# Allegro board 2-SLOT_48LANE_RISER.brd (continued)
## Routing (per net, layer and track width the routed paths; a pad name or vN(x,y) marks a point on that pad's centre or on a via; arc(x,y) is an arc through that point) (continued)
PE_SLOT1_RX_DN<13>: length 121.3
  IN2 w0.089: v5(128.89,79.56) 129.07,79.38 129.07,77.6 129.03,77.55 129.03,77.53
  IN2 w0.145: J1.A73 222.2,34.51 222.4,34.44 222.54,34.52 222.68,34.66 222.68,38.06 222.53,38.35 222.08,38.73 221.76,39.04 221.69,39.45 221.69,40.24 221.59,40.77 220.94,41.7 220.29,42.63 220.12,43.61 220.12,43.61 219.96,44.54 219.84,44.62 219.72,45.33 219.8,45.45 219.7,46.02 219.62,46.07 219.48,46.84 219.54,46.92 219.19,48.86 218.18,50.31 216.27,51.64 215.22,51.83 215.09,51.74 214.6,51.82 214.51,51.95 214.11,52.02 213.98,51.93 213.49,52.02 213.4,52.15 211.82,52.43 205.03,53.62 204.21,53.77 204.08,53.68 203.59,53.76 203.5,53.9 203.1,53.96 202.97,53.87 202.48,53.96 202.39,54.09 201.56,54.24 200.16,54.48 191.93,53.03 143.93,61.5 139.47,64.62 139.33,64.59 138.73,65.01 138.7,65.15 138.23,65.49 138.05,65.45 137.49,65.85 137.46,66.02 136.99,66.36 136.82,66.33 136.25,66.73 136.22,66.89 135.74,67.23 135.56,67.19 135.01,67.58 134.98,67.76 133.76,68.62 131.5,70.88 131.32,70.88 130.94,71.26 130.94,71.43 129.03,73.35 129.03,74.31 128.87,74.47 128.87,75 129.03,75.15 129.03,75.59 128.89,75.72 128.89,76.25 129.03,76.39 129.03,77.53
  BOTTOM w0.135: U1.R4 v5(128.89,79.56)
PE_SLOT1_RX_DN<14>: length 118.6
  IN2 w0.089: 127.35,77.36 127.35,77.38 127.39,77.42 127.39,77.63 126.69,78.32 126.69,79 126.91,79.22 126.91,79.78 v5(127.29,80.36)
  IN2 w0.145: J1.A77 218.2,34.51 218.4,34.44 218.54,34.52 218.68,34.66 218.68,37.73 218.61,38.12 218.4,38.53 218.09,38.85 217.71,39.39 217.71,40.13 217.55,41 216.23,42.88 215.99,44.29 216.24,45.72 216.09,46.56 215.87,46.88 215.64,47.19 215.51,47.22 215.12,47.78 215.14,47.91 215.14,47.92 214.79,48.42 210.68,51.29 200.06,53.19 192.77,51.9 142.55,60.76 133.16,67.33 127.35,73.14 127.35,77.36
  BOTTOM w0.135: U1.U5 v5(127.29,80.36)
PE_SLOT1_RX_DN<15>: length 116.2
  IN2 w0.089: v5(126.49,80.36) 126.11,79.78 126.11,77.84 126.25,77.7 126.25,77.01 126.21,76.96 126.21,76.94
  IN2 w0.145: 126.21,76.94 126.21,72.58 133.99,64.8 140.65,60.13 192.88,50.92 199.74,52.13 208.15,50.65 208.35,50.51 208.35,50.51 208.37,50.35 208.76,50.08 208.92,50.11 210.07,49.3 210.08,49.3 211.61,48.22 212.59,46.83 213.67,40.72 213.67,40.03 213.8,39.25 214.68,38 214.68,34.66 214.54,34.52 214.4,34.44 214.2,34.51 J1.A81
  BOTTOM w0.135: U1.V5 v5(126.49,80.36)
PE_SLOT1_RX_DP<0>: length 162
  IN2 w0.089: v5(137.69,85.16) 138.22,85.53 141.16,85.53 142.29,86.67 143.16,86.67 143.21,86.71 143.23,86.71
  IN2 w0.145: J1.A16 278.46,34 278.52,34.2 278.7,34.29 278.97,34.55 278.97,38.23 277.93,39.27 277.93,40.74 277.57,41.25 276.31,43.04 276.01,44.74 274.93,46.29 255.86,59.64 196.49,70.11 188.2,75.92 161.63,80.6 155.06,85.2 152.33,85.68 152.33,85.68 146.48,86.71 143.23,86.71
  BOTTOM w0.135: U1.E11 v5(137.69,85.16)
PE_SLOT1_RX_DP<1>: length 159.6
  IN2 w0.089: v5(137.69,84.36) 138.22,84.73 138.74,84.73 138.94,84.94 139.8,84.94 140.08,84.66 143.22,84.66 143.26,84.7 143.28,84.7
  IN2 w0.145: 143.28,84.7 144.63,84.7 155.99,82.7 160.11,79.82 186.96,75.08 195.61,69.03 198.26,68.56 254.13,58.71 268.04,48.97 268.13,48.48 267.51,47.6 267.56,47.33 267.78,47.17 268.05,47.22 268.67,48.1 269.16,48.19 270.58,47.2 272.09,45.03 272.59,42.19 273.97,40.23 273.97,39.22 272.97,38.22 272.97,34.67 273.12,34.52 273.26,34.44 273.46,34.51 J1.A21
  BOTTOM w0.135: U1.E10 v5(137.69,84.36)
PE_SLOT1_RX_DP<2>: length 152.9
  IN2 w0.089: 143.28,83.18 143.26,83.18 143.22,83.13 142.71,83.13 142.47,83.38 139.88,83.38 139.64,83.13 138.22,83.13 v5(137.69,82.76)
  IN2 w0.145: J1.A25 269.46,34.51 269.26,34.44 269.26,34.45 269.12,34.52 268.97,34.67 268.97,38.15 269.95,39.14 269.95,40.76 267.97,43.58 267.7,45.11 265.13,48.78 252.1,57.9 198.26,67.4 194.17,68.12 185.73,74.03 159.49,78.65 155.02,81.78 145.95,83.38 143.76,83.18 143.28,83.18
  BOTTOM w0.135: U1.E8 v5(137.69,82.76)
PE_SLOT1_RX_DP<3>: length 152.2
  IN2 w0.089: v5(137.69,81.96) 138.22,82.33 138.74,82.33 138.94,82.54 140.82,82.54 140.83,82.53 142.73,82.2 143.22,82.2 143.26,82.24 143.28,82.24
  IN2 w0.145: J1.A29 265.46,34.51 265.26,34.44 265.12,34.52 264.97,34.67 264.97,38.26 263.97,39.26 263.97,40.37 263.7,41.89 263.52,42.15 263.41,42.31 262.84,45.57 262.82,45.63 262.1,46.65 261.35,47.73 260.85,47.82 260.32,47.45 260.12,47.48 259.91,47.78 259.95,47.98 260.48,48.35 260.56,48.85 260.28,49.26 259.78,49.35 258.89,48.72 258.62,48.77 258.47,48.99 258.52,49.26 259.41,49.88 259.49,50.38 258.85,51.29 250.77,56.95 240.97,58.68 198.31,66.2 198.26,66.21 193.61,67.19 185.38,72.96 159.25,77.56 154.74,80.72 146.12,82.24 143.28,82.24
  BOTTOM w0.135: U1.E7 v5(137.69,81.96)
PE_SLOT1_RX_DP<4>: length 143.2
  IN2 w0.089: v5(137.69,80.36) 138.22,80.73 139.34,80.73 140.16,80.88 142.87,80.88 142.91,80.92 142.94,80.92
  IN2 w0.145: J1.A35 259.46,34.51 259.26,34.44 259.12,34.52 258.97,34.67 258.97,38.24 259.97,39.24 259.97,40.33 259.88,40.88 259.88,40.88 258.64,42.64 258.4,42.88 257.87,43.63 257.49,45.81 252.28,53.24 248.01,56.23 236.29,58.3 236.23,58.31 198.26,65.01 193.48,65.85 184.99,71.8 158.51,76.46 154.41,79.33 145.37,80.92 142.94,80.92
  BOTTOM w0.135: U1.E5 v5(137.69,80.36)
PE_SLOT1_RX_DP<5>: length 141.8
  IN2 w0.089: v5(137.69,79.56) 138.22,79.93 138.74,79.93 138.94,80.14 141.94,80.14 142.22,79.86 142.61,79.86 142.65,79.9 142.68,79.9
  IN2 w0.145: 142.68,79.9 145.23,79.9 153.43,78.46 155.01,77.35 155.1,76.86 154.58,76.11 154.63,75.85 154.85,75.69 155.11,75.74 155.63,76.48 156.13,76.57 158.1,75.19 184.3,70.57 192.36,64.92 245.15,55.62 249.74,52.4 253.27,47.37 254.03,43.05 255.05,41.59 255.85,40.76 255.96,40.15 255.96,39.24 254.97,38.25 254.97,34.67 255.12,34.52 255.26,34.44 255.46,34.51 J1.A39
  BOTTOM w0.135: U1.E4 v5(137.69,79.56)
PE_SLOT1_RX_DP<6>: length 134.8
  IN2 w0.089: 141.12,78.3 141.1,78.3 141.05,78.26 140.08,78.26 139.8,78.54 138.94,78.54 138.74,78.33 138.22,78.33 v5(137.69,77.96)
  IN2 w0.145: J1.A43 251.46,34.51 251.26,34.44 251.12,34.52 250.97,34.67 250.97,38.21 251.94,39.19 251.94,39.97 251.82,40.69 250.32,42.84 249.86,45.42 245.15,52.15 240.8,55.2 190.59,64.05 183.2,69.22 155.13,74.18 149.82,77.89 144.86,78.77 143.84,78.77 143.28,78.66 141.4,78.3 141.12,78.3
  BOTTOM w0.135: U1.E2 v5(137.69,77.96)
PE_SLOT1_RX_DP<7>: length 132.4
  IN2 w0.089: v5(137.69,77.16) 138.22,77.53 140.7,77.53 140.74,77.58 140.77,77.58
  IN2 w0.145: J1.A47 247.46,34.51 247.26,34.44 247.12,34.52 246.97,34.67 246.97,38.23 246.02,39.17 246.02,40.7 245.89,41.45 243.51,44.84 242.42,51.05 241.73,52.03 238.11,54.56 189.65,63.11 182.8,67.9 154.81,72.84 152.51,74.45 152.01,74.36 151.4,73.48 151.13,73.43 150.91,73.59 150.86,73.85 151.48,74.74 151.39,75.23 149.05,76.87 145.03,77.58 140.77,77.58
  BOTTOM w0.135: U1.E1 v5(137.69,77.16)
PE_SLOT1_RX_DP<8>: length 129.3
  IN2 w0.089: 135.71,76.68 135.71,76.7 135.66,76.75 135.66,79.78 v5(135.29,80.36)
  IN2 w0.145: 135.71,76.68 135.71,76.33 135.94,76.1 139.52,76.1 140.06,76.63 140.55,76.63 143.28,76.15 146.41,75.6 150.92,72.44 155.28,71.67 155.28,71.67 182.23,66.92 189.21,62.04 225.33,55.67 237.76,46.96 238.59,45.78 241.97,40.95 241.97,39.36 242.95,38.38 242.95,34.54 242.7,34.29 242.52,34.2 242.46,34 J1.A52
  BOTTOM w0.135: U1.H5 v5(135.29,80.36)
PE_SLOT1_RX_DP<9>: length 126.9
  IN2 w0.089: v5(134.49,80.36) 134.86,79.78 134.86,79.25 135.1,79.01 135.1,78.18 134.69,77.76 134.69,77.7 134.67,77.68
  IN2 w0.145: 134.67,77.68 134.43,77.44 134.43,76.34 136.04,74.73 141.06,74.73 146.41,73.78 150.11,71.19 181.82,65.6 188.23,61.11 223.46,54.89 231.22,49.46 233.68,47 235.41,44.53 237.97,40.58 237.97,39.34 238.96,38.34 238.96,34.55 238.7,34.29 238.52,34.2 238.51,34.19 238.45,34.01 J1.A56
  BOTTOM w0.135: U1.J5 v5(134.49,80.36)
PE_SLOT1_RX_DP<10>: length 125.6
  IN2 w0.089: v5(132.89,80.36) 133.26,79.78 133.26,77.95 132.69,77.37 132.69,76.7 132.73,76.66 132.73,76.64
  IN2 w0.145: J1.A60 234.49,33.94 234.58,34.23 234.7,34.29 234.97,34.55 234.97,38.34 233.99,39.31 233.99,40.41 233.88,41.08 231.82,44.02 227.8,49.76 221.24,54.36 186.22,60.53 186.22,60.53 181.02,64.17 135.37,72.22 134.32,72.95 134.06,73.33 133.82,74.71 132.73,75.79 132.73,76.64
  BOTTOM w0.135: U1.L5 v5(132.89,80.36)
PE_SLOT1_RX_DP<11>: length 123.7
  IN2 w0.089: v5(132.09,80.36) 132.46,79.78 132.46,79.25 132.74,78.97 132.74,78.51 131.86,77.63 131.86,76.8 131.91,76.76 131.91,76.74
  IN2 w0.145: 131.91,76.74 131.91,74.93 132.43,74.41 132.66,73.08 133.02,72.56 135.03,71.16 179.76,63.27 184.63,59.86 219.53,53.71 222.39,51.89 229.71,41.43 229.97,40 229.97,39.35 230.96,38.35 230.96,34.55 230.7,34.29 230.51,34.19 230.45,34.01 J1.A64
  BOTTOM w0.135: U1.M5 v5(132.09,80.36)
PE_SLOT1_RX_DP<12>: length 123.2
  IN2 w0.089: v5(129.69,80.36) 130.06,79.78 130.06,78.12 130.3,77.88 130.3,77.29 130.35,77.25 130.35,77.23
  IN2 w0.145: J1.A68 226.46,34 226.52,34.2 226.7,34.29 226.96,34.55 226.96,38.35 225.98,39.34 225.98,40.37 225.8,41.38 224.56,43.15 224.07,45.95 223.68,46.5 223.68,46.51 222.65,47.99 220.7,50.77 217.59,52.94 215.39,53.33 200.72,55.92 191.62,54.31 144.62,62.6 134.44,69.72 130.95,73.22 130.95,74.87 130.35,75.47 130.35,77.23
  BOTTOM w0.135: U1.P5 v5(129.69,80.36)
PE_SLOT1_RX_DP<13>: length 121.2
  IN2 w0.089: 129.31,77.53 129.31,77.55 129.26,77.6 129.26,79.78 v5(128.89,80.36)
  IN2 w0.145: 129.31,77.53 129.31,73.46 133.94,68.83 144.04,61.76 191.93,53.32 200.16,54.77 201.6,54.51 201.67,54.5 201.68,54.5 202.02,54.44 216.38,51.91 218.38,50.51 219.46,48.97 220.56,42.74 221.17,41.86 221.86,40.88 221.97,40.26 221.97,39.47 222.02,39.18 222.26,38.94 222.75,38.53 222.96,38.13 222.96,34.55 222.7,34.29 222.52,34.2 222.46,34 J1.A72
  BOTTOM w0.135: U1.R5 v5(128.89,80.36)
PE_SLOT1_RX_DP<14>: length 118.7
  IN2 w0.089: v5(127.29,79.56) 127.1,79.38 127.1,79.14 126.88,78.92 126.88,78.4 127.58,77.7 127.58,77.43 127.63,77.38 127.63,77.36
  IN2 w0.145: 127.63,77.36 127.63,76.38 127.75,76.26 127.75,75.75 127.63,75.63 127.63,75.18 127.75,75.06 127.75,74.55 127.63,74.43 127.63,73.25 128,72.88 128.19,72.88 128.66,72.41 128.66,72.23 129.07,71.81 129.27,71.81 129.73,71.36 129.73,71.16 129.98,70.9 130.21,70.9 130.63,70.47 130.63,70.25 130.92,69.96 131.11,69.96 131.57,69.49 131.57,69.31 133.34,67.55 142.66,61.02 192.77,52.19 200.06,53.47 210.79,51.56 214.99,48.62 216.35,46.67 216.52,45.72 216.27,44.29 216.5,42.99 217.82,41.11 217.98,40.16 217.98,39.48 218.3,39.03 218.63,38.7 218.88,38.21 218.96,37.76 218.96,34.55 218.7,34.29 218.52,34.2 218.46,34 J1.A76
  BOTTOM w0.135: U1.U4 v5(127.29,79.56)
PE_SLOT1_RX_DP<15>: length 116.2
  IN2 w0.089: 126.49,76.94 126.49,76.96 126.44,77.01 126.44,77.77 126.3,77.91 126.3,79.38 v5(126.49,79.56)
  IN2 w0.145: J1.A80 214.46,34 214.52,34.2 214.7,34.29 214.96,34.55 214.96,38.09 214.07,39.36 213.95,40.06 213.95,40.74 212.85,46.94 211.82,48.42 211.01,48.99 210.24,49.53 210.24,49.53 208.26,50.91 199.74,52.41 192.88,51.2 140.76,60.39 134.17,65.01 132.19,66.99 132.19,67.16 131.82,67.53 131.65,67.53 131.28,67.9 131.28,68.07 130.91,68.44 130.74,68.44 130.34,68.84 130.34,69.01 129.97,69.38 129.8,69.38 129.43,69.75 129.43,69.92 129.06,70.29 128.89,70.29 128.36,70.82 128.36,70.99 127.99,71.36 127.82,71.36 127.45,71.73 127.45,71.9 127.08,72.27 126.92,72.27 126.49,72.69 126.49,76.94
  BOTTOM w0.135: U1.V4 v5(126.49,79.56)
PE_SLOT1_TX_C_DN<0>: length 154.4
  BOTTOM w0.135: C31.1 281.92,44.82 281.92,45.6 281.47,46.24 281.14,46.62 278.44,48.5 274.21,49.25 268.95,52.93 268.95,52.93 268.01,53.59 256.44,61.69 211.77,69.57 v8(210.18,70.68) 197.22,79.76 165.93,85.28 163.63,86.89 150.19,89.26 148.3,88.93 147.18,88.14 147,88.18 146.5,87.83 146.47,87.64 146.03,87.33 145.86,87.36 145.34,87 145.31,86.83 144.59,86.33 143.36,86.11 142.96,85.83 142.59,85.46 142.04,85.46 141.9,85.6 141.45,85.6 141.32,85.46 140.59,85.46 U1.A11
PE_SLOT1_TX_C_DN<1>: length 153
  BOTTOM w0.135: C32.1 273.97,44.81 273.97,45.48 273.72,46.86 273.09,47.75 270.02,49.9 269.51,49.81 268.99,49.07 268.73,49.02 268.51,49.18 268.47,49.44 268.99,50.18 268.9,50.69 268.47,50.99 267.93,50.89 267.52,50.31 267.25,50.26 267.04,50.42 267,50.64 267.43,51.27 267.34,51.78 266.92,52.08 266.41,51.99 265.98,51.37 265.7,51.32 265.48,51.48 265.44,51.73 265.88,52.36 265.79,52.87 265.01,53.41 264.97,53.62 264.53,53.93 264.33,53.89 263.89,54.2 263.85,54.4 263.41,54.71 263.21,54.68 262.41,55.23 261.42,55.93 259.84,57.03 254.43,60.82 v8(214,67.95) 212.54,68.21 211.31,68.42 196.83,78.57 165.01,84.18 162.84,85.7 150.28,87.91 149.08,87.7 147.32,86.47 147.1,86.51 146.64,86.19 146.6,85.97 146.16,85.66 145.95,85.7 145.5,85.39 145.47,85.17 145.14,84.94 143.55,84.66 140.59,84.66 U1.A10
PE_SLOT1_TX_C_DN<2>: length 142
  BOTTOM w0.135: U1.A8 140.59,83.06 141.03,83.06 141.17,83.21 141.58,83.21 141.73,83.06 142.07,83.06 142.47,83.46 145.86,83.46 147.77,84.8 147.81,85 148.25,85.31 148.45,85.27 149.14,85.75 149.77,85.87 149.89,86.03 150.42,86.12 150.58,86.01 152.11,86.28 152.24,86.28 152.25,86.28 152.46,86.28 161.63,84.66 164.15,82.89 165.28,82.69 165.45,82.8 166.03,82.7 166.14,82.54 166.67,82.45 166.79,82.53 167.45,82.41 167.53,82.29 196.17,77.25 v8(203.07,72.42) 211.3,66.65 250.24,59.79 269.27,46.46 269.56,46.17 269.96,45.6 269.96,44.82 C33.1
PE_SLOT1_TX_C_DN<3>: length 139.8
  BOTTOM w0.135: U1.A7 140.59,82.26 141.23,82.26 141.39,82.42 141.75,82.42 141.91,82.26 142.1,82.26 142.1,82.26 142.43,82.26 142.57,82.4 143.11,82.4 143.24,82.26 146.27,82.26 146.34,82.27 149.52,84.5 151.59,84.87 161.04,83.2 163.62,81.39 196.35,75.62 v8(199.71,73.27) 210.89,65.44 247.39,59 248.64,58.13 248.87,58.17 249.32,57.86 249.36,57.63 254.31,54.16 260.78,49.63 260.86,49.15 260.64,48.83 260.69,48.54 260.91,48.39 261.17,48.43 261.4,48.75 261.91,48.84 262.33,48.55 262.42,48.03 262.2,47.72 262.24,47.45 262.46,47.3 262.73,47.35 262.95,47.67 263.46,47.75 264.58,46.97 265.64,46.23 265.9,45.85 265.96,45.53 265.96,44.82 C34.1
PE_SLOT1_TX_C_DN<4>: length 130.9
  BOTTOM w0.135: U1.A5 140.59,80.66 140.91,80.66 141.07,80.82 141.3,80.82 141.46,80.66 141.68,80.66 142.07,81.06 142.45,81.06 142.59,81.19 142.95,81.19 143.08,81.06 v8(146.38,81.06) 146.75,81.06 147.47,81.19 149.91,82.9 151.87,83.24 160.61,81.7 162.94,80.07 195.75,74.28 210.38,64.04 242.08,58.45 242.89,57.89 243.03,57.91 243.58,57.52 243.61,57.38 259.5,46.25 259.81,45.81 259.96,45.6 259.96,44.82 C67.1
PE_SLOT1_TX_C_DN<5>: length 128.7
  BOTTOM w0.135: C68.1 255.96,44.82 255.96,45.25 255.09,47.33 254.58,48.07 252.21,49.73 251.6,49.62 251.29,49.18 251.01,49.13 250.58,49.43 250.54,49.67 250.86,50.13 250.75,50.75 250.24,51.11 249.63,51 249.55,50.89 249.19,50.83 246.33,52.83 246.33,52.83 v8(245.23,53.6) 244.03,54.44 241.57,56.16 241.53,56.36 241.09,56.67 240.9,56.63 239.92,57.32 209.42,62.7 195.36,72.54 163.17,78.22 159.87,80.53 152.73,81.79 152.51,81.79 152.51,81.79 152.38,81.79 149.82,81.34 147.71,79.86 143.06,79.86 142.88,80.04 142.54,80.04 142.37,79.86 141.86,79.86 141.71,80.01 141.27,80.01 141.12,79.86 140.59,79.86 U1.A4
PE_SLOT1_TX_C_DN<6>: length 122.4
  BOTTOM w0.135: U1.A2 140.59,78.26 140.95,78.26 141.1,78.41 141.43,78.41 141.58,78.26 141.92,78.26 142.09,78.44 142.32,78.44 142.5,78.26 142.76,78.26 143.15,78.66 v8(147.04,78.66) 148.17,78.66 148.51,78.71 150.16,79.87 152.28,80.25 159.9,78.9 162.73,76.92 195.01,71.23 210.49,60.38 239.61,55.25 240.29,54.78 240.41,54.8 240.96,54.42 240.98,54.29 241.42,53.98 241.63,54.02 242.07,53.71 242.11,53.5 250.98,47.29 251.83,46.08 251.87,46.01 251.96,45.53 251.96,44.82 C69.1
PE_SLOT1_TX_C_DN<7>: length 120.2
  BOTTOM w0.135: C70.1 247.96,44.82 247.96,47.07 247.59,47.64 247.24,48.17 245.64,49.29 245.13,49.2 245.01,49.04 244.75,48.99 244.53,49.14 244.48,49.41 244.6,49.57 244.51,50.08 244.08,50.38 243.57,50.29 243.46,50.12 243.2,50.08 242.98,50.23 242.93,50.49 243.05,50.66 242.96,51.17 240.57,52.84 240.55,52.96 240.15,53.24 240.03,53.22 239.66,53.48 v8(238.18,53.74) 236.52,54.03 210.9,58.55 194.48,70.04 161.81,75.81 159.54,77.39 152.15,78.69 151.03,78.5 149.66,77.54 148.98,77.42 143.26,77.42 143.16,77.52 142.78,77.52 142.67,77.42 142.37,77.42 142.24,77.55 141.94,77.55 141.81,77.42 141.48,77.42 141.35,77.55 141.02,77.55 140.9,77.42 140.63,77.42 U1.A1
PE_SLOT1_TX_C_DN<8>: length 122.3
  BOTTOM w0.135: U1.H1 134.8,77.47 134.8,77.12 135.02,76.89 135.25,76.89 135.63,76.51 135.63,76.28 135.86,76.05 136.05,76.05 136.2,76.2 136.45,76.2 136.6,76.05 137.24,76.05 137.41,76.23 137.67,76.23 137.85,76.05 138.13,76.05 138.3,76.22 138.59,76.22 138.76,76.05 139.35,76.05 139.88,76.58 140.74,76.58 141.12,76.2 141.43,76.2 141.58,76.35 141.94,76.35 142.09,76.2 142.52,76.2 142.67,76.35 143.08,76.35 143.23,76.2 150.46,76.2 153.88,76.8 159.39,75.83 161.26,74.52 190.41,69.38 v8(192.25,69.06) 194.32,68.69 211.64,56.56 237.79,51.95 237.91,51.9 237.92,51.9 238.52,51.65 239.14,51.21 239.35,51.25 239.8,50.94 239.83,50.73 244.8,47.25 245.92,45.65 245.92,44.82 C71.1
PE_SLOT1_TX_C_DN<9>: length 120.9
  BOTTOM w0.135: C72.1 241.94,44.82 241.94,45.53 241.7,46.86 241.2,47.57 239.73,48.6 239.22,48.51 239.03,48.25 238.77,48.2 238.55,48.35 238.51,48.62 238.69,48.88 238.6,49.39 237.47,50.19 237.43,50.38 236.99,50.69 236.8,50.65 236.48,50.88 236.41,50.89 236.41,50.89 211.33,55.32 194.41,67.16 192.54,67.49 v8(191.16,67.74) 160.85,73.08 158.62,74.65 156.87,74.96 143.23,74.96 143.13,75.06 142.75,75.06 142.49,74.79 140.9,74.79 140.73,74.96 140.19,74.96 140.03,74.79 139.49,74.79 139.33,74.96 138.79,74.96 138.63,74.79 138.09,74.79 137.93,74.96 137.39,74.96 137.23,74.79 136.69,74.79 136.53,74.96 135.99,74.96 135.83,74.79 135.37,74.79 135.07,75.1 135.07,75.32 134.82,75.56 134.6,75.56 134.37,75.79 134.37,76.28 133.99,76.65 133.99,77.47 U1.J1
PE_SLOT1_TX_C_DN<10>: length 118.9
  BOTTOM w0.135: U1.L1 132.39,77.47 132.39,76.37 133.15,75.62 133.33,75.62 133.71,75.23 133.71,75.06 133.94,74.83 133.94,74.3 133.81,74.17 133.81,73.28 134.39,72.69 135.31,72.69 135.46,72.85 136,72.85 136.15,72.69 136.69,72.69 136.84,72.85 137.38,72.85 137.53,72.69 138.07,72.69 138.22,72.85 138.76,72.85 138.91,72.69 139.45,72.69 139.6,72.85 140.14,72.85 140.29,72.69 140.83,72.69 140.99,72.85 141.52,72.85 141.68,72.69 142.09,72.69 143.15,73.75 v8(153.9,73.75) 156.09,73.75 157.82,73.45 160.2,71.79 194.01,65.82 210.8,54.07 232.26,50.28 237.84,46.38 237.97,45.6 237.97,44.82 C73.1
PE_SLOT1_TX_C_DN<11>: length 116.7
  BOTTOM w0.135: U1.M1 131.6,77.47 131.6,76.43 131.7,76.32 131.7,76.03 131.6,75.92 131.6,75.47 131.83,75.24 131.98,75.24 132.21,75.01 132.21,74.85 132.56,74.5 132.56,72.8 134.06,71.3 134.91,71.3 135.06,71.45 135.6,71.45 135.75,71.3 136.29,71.3 136.44,71.45 136.98,71.45 137.14,71.3 137.67,71.3 137.83,71.45 138.37,71.45 138.52,71.3 139.06,71.3 139.21,71.45 139.75,71.45 139.9,71.3 140.44,71.3 140.59,71.45 141.13,71.45 141.28,71.3 142.39,71.3 143.65,72.55 155.4,72.55 157.08,72.26 157.08,72.26 157.15,72.25 159.47,70.62 193.58,64.6 211.01,52.4 220.63,50.7 v8(222.24,50.42) 230.81,48.9 231.05,48.74 231.29,48.78 231.73,48.47 231.77,48.23 232.82,47.5 233.95,45.89 234.01,45.53 234.01,44.82 C74.1
PE_SLOT1_TX_C_DN<12>: length 114.8
  BOTTOM w0.135: C75.1 229.97,44.82 229.97,45.9 229.4,46.72 227.56,48.01 227.55,48.02 227.48,48.03 210.81,50.97 193.09,63.38 158.63,69.46 156.14,71.2 155.3,71.35 v8(154.08,71.35) 144.15,71.35 142.7,69.9 139.22,69.9 139.15,69.98 138.46,69.98 138.38,69.9 137.84,69.9 137.69,70.05 137.15,70.05 137,69.9 136.46,69.9 136.31,70.05 135.77,70.05 135.62,69.9 135.08,69.9 134.93,70.05 134.39,70.05 134.24,69.9 133.38,69.9 132.81,70.47 132.81,70.67 132.43,71.06 132.22,71.06 131.84,71.44 131.84,71.64 131.46,72.02 131.26,72.02 130.92,72.36 130.92,74.62 130.67,74.87 130.67,75.04 130.44,75.27 130.27,75.27 129.99,75.54 129.99,75.97 130.1,76.08 130.1,76.58 129.99,76.69 129.99,77.47 U1.P1
PE_SLOT1_TX_C_DN<13>: length 112.5
  BOTTOM w0.135: U1.R1 129.2,77.47 129.2,74.74 129.41,74.52 129.41,73.15 129.54,73.03 129.54,72.42 129.41,72.29 129.41,71.63 129.79,71.25 130.07,71.25 130.45,70.87 130.45,70.59 130.84,70.21 131.12,70.21 131.5,69.83 131.5,69.55 132.59,68.45 133.3,68.45 133.48,68.63 134.01,68.63 134.19,68.45 134.73,68.45 134.91,68.63 135.45,68.63 135.62,68.45 136.16,68.45 136.34,68.63 136.88,68.63 137.06,68.45 v8(140.57,68.45) 142.95,68.45 144.42,69.93 155.68,69.93 155.85,69.77 157.98,68.27 192.23,62.23 209.86,49.88 210.36,49.79 222.33,47.68 225.46,46.13 225.94,45.69 226.04,45.48 226.04,44.82 C76.1
PE_SLOT1_TX_C_DN<14>: length 110.9
  BOTTOM w0.135: C77.1 222.06,44.8 222.06,45.34 221.47,45.93 220.23,46.8 208.85,48.81 191.32,61.08 157.64,67.02 155.31,68.65 144.85,68.65 143.22,67.03 v8(137.42,67.03) 136.44,67.03 136.23,67.23 135.69,67.23 135.49,67.03 134.95,67.03 134.75,67.23 134.21,67.23 134.01,67.03 133.47,67.03 133.27,67.23 132.73,67.23 132.52,67.03 131.65,67.03 130.51,68.17 130.51,68.31 130.52,68.31 130.52,68.44 130.13,68.83 129.99,68.83 129.86,68.83 129.47,69.21 129.47,69.35 129.47,69.49 129.09,69.87 128.95,69.87 128.81,69.87 128.09,70.59 128.09,71.32 128.2,71.42 128.2,72.11 128.09,72.21 128.09,73.28 127.92,73.45 127.92,75.27 128.02,75.36 128.02,76.07 127.6,76.5 127.6,77.47 U1.U1
PE_SLOT1_TX_C_DN<15>: length 110.9
  BOTTOM w0.135: C78.1 218.06,44.8 218.06,45.23 218.03,45.26 217.91,45.41 217.69,45.68 217.69,45.68 212.87,46.53 212.44,46.23 212.31,45.49 212.09,45.34 211.83,45.39 211.68,45.6 211.81,46.35 211.51,46.77 211.08,47.04 207.96,47.59 190.44,59.86 157.47,65.67 154.93,67.45 145.35,67.45 143.53,65.63 v8(138.23,65.63) 135.72,65.63 135.57,65.79 135.03,65.79 134.88,65.63 134.34,65.63 134.19,65.79 133.65,65.79 133.49,65.63 132.96,65.63 132.8,65.79 132.27,65.79 132.11,65.63 131.01,65.63 130.38,66.27 130.38,66.49 130,66.87 129.77,66.87 129.39,67.26 129.39,67.48 129.01,67.86 128.78,67.86 128.4,68.25 128.4,68.47 128.02,68.85 127.79,68.85 126.67,69.98 126.67,70.35 126.82,70.5 126.82,71.04 126.67,71.19 126.67,71.73 126.82,71.88 126.82,72.42 126.67,72.57 126.67,76.58 126.77,76.68 126.77,77.45 U1.V1
PE_SLOT1_TX_C_DP<0>: length 154.5
  BOTTOM w0.135: C27.1 281.62,44.82 281.62,45.5 281.23,46.05 280.94,46.38 278.32,48.21 274.09,48.96 268.31,53.01 267.83,53.34 267.83,53.34 267.36,53.68 267.36,53.67 256.32,61.41 211.65,69.28 210.01,70.43 v8(208.95,71.17) 197.1,79.47 165.81,84.99 163.51,86.6 156.85,87.78 150.19,88.95 148.42,88.64 147.89,88.27 144.71,86.04 143.48,85.82 143.28,85.69 143.16,85.6 142.72,85.16 140.09,85.16 139.94,85.31 U1.B11
PE_SLOT1_TX_C_DP<1>: length 153
  BOTTOM w0.135: C28.1 273.66,44.83 273.66,45.45 273.43,46.74 272.87,47.53 269.95,49.58 269.69,49.53 269.17,48.79 268.66,48.7 268.23,49 268.14,49.51 268.66,50.25 268.62,50.51 268.4,50.67 268.1,50.61 267.69,50.03 267.18,49.94 266.76,50.24 266.67,50.71 267.11,51.34 267.06,51.6 266.85,51.75 266.58,51.71 266.15,51.09 265.63,51 265.2,51.3 265.12,51.8 265.56,52.43 265.51,52.69 259.72,56.74 254.31,60.53 v8(212.49,67.91) 211.19,68.14 196.71,78.28 164.89,83.89 162.72,85.41 150.28,87.61 149.2,87.42 147.39,86.15 145.26,84.65 143.57,84.36 140.09,84.36 139.94,84.51 U1.B10
PE_SLOT1_TX_C_DP<2>: length 141.9
  BOTTOM w0.135: U1.B8 139.94,82.91 140.09,82.76 142.2,82.76 142.59,83.16 145.96,83.16 147.95,84.55 149.26,85.46 152.11,85.97 152.24,85.97 152.25,85.97 152.44,85.97 161.51,84.37 164.04,82.6 196.05,76.96 v8(201.53,73.13) 202.89,72.17 211.18,66.37 250.13,59.5 269.08,46.23 269.32,45.98 269.65,45.5 269.65,44.82 C29.1
PE_SLOT1_TX_C_DP<3>: length 139.9
  BOTTOM w0.135: U1.B7 139.94,82.11 140.09,81.96 141.97,81.96 141.97,81.95 146.3,81.95 146.46,81.98 149.64,84.21 151.59,84.56 160.92,82.91 163.5,81.1 196.23,75.33 v8(198.21,73.94) 199.53,73.02 210.77,65.15 247.27,58.72 254.22,53.86 260.5,49.46 260.54,49.22 260.32,48.9 260.41,48.37 260.84,48.07 261.09,48.11 261.35,48.16 261.57,48.47 261.83,48.52 262.05,48.37 262.1,48.11 261.88,47.79 261.97,47.28 262.39,46.98 262.9,47.07 263.13,47.39 263.39,47.43 265.41,46.02 265.61,45.73 265.65,45.5 265.65,44.82 C30.1
PE_SLOT1_TX_C_DP<4>: length 131
  BOTTOM w0.135: U1.B5 139.94,80.51 140.09,80.36 141.8,80.36 142.2,80.75 v8(144.98,80.75) 146.78,80.75 147.59,80.9 150.03,82.61 151.87,82.93 160.49,81.41 162.82,79.78 195.63,73.99 210.26,63.75 241.96,58.16 259.28,46.03 259.56,45.64 259.56,45.63 259.65,45.5 259.65,44.82 C55.1
PE_SLOT1_TX_C_DP<5>: length 128.8
  BOTTOM w0.135: C56.1 255.65,44.82 255.65,45.19 254.82,47.19 254.36,47.85 252.14,49.41 251.78,49.34 251.47,48.91 250.93,48.81 250.3,49.25 250.22,49.74 250.54,50.21 250.48,50.57 250.17,50.78 249.81,50.72 249.73,50.61 249.12,50.51 v8(243.86,54.19) 243.27,54.6 239.8,57.03 209.3,62.41 195.24,72.25 163.05,77.93 159.75,80.24 152.7,81.48 152.51,81.48 152.51,81.48 152.38,81.48 149.94,81.05 147.8,79.55 142.88,79.55 142.88,79.56 140.09,79.56 139.94,79.71 U1.B4
PE_SLOT1_TX_C_DP<6>: length 122.4
  BOTTOM w0.135: U1.B2 139.94,78.11 140.09,77.96 142.88,77.96 143.27,78.35 v8(145.24,78.35) 148.2,78.35 148.63,78.43 150.28,79.58 152.28,79.94 159.78,78.61 162.61,76.63 194.89,70.94 210.37,60.1 239.49,54.96 250.76,47.07 251.17,46.49 251.58,45.91 251.58,45.9 251.65,45.5 251.65,44.82 C57.1
PE_SLOT1_TX_C_DP<7>: length 120.2
  BOTTOM w0.135: U1.B1 139.94,77.56 140.39,77.11 149.01,77.11 149.78,77.25 151.15,78.21 152.15,78.38 159.42,77.1 161.69,75.52 194.36,69.76 210.78,58.26 v8(236.47,53.73) 239.54,53.19 242.68,50.99 242.72,50.73 242.61,50.57 242.7,50.06 243.12,49.76 243.63,49.85 243.75,50.01 244.01,50.06 244.23,49.91 244.28,49.64 244.16,49.48 244.25,48.97 244.68,48.67 245.19,48.76 245.3,48.93 245.57,48.97 247.01,47.96 247.65,46.98 247.65,44.82 C58.1
PE_SLOT1_TX_C_DP<8>: length 122.3
  BOTTOM w0.135: U1.H2 134.49,77.96 134.49,76.99 135.74,75.74 139.47,75.74 140.01,76.28 140.62,76.28 141,75.9 150.49,75.9 153.88,76.49 159.27,75.54 161.14,74.23 v8(190.36,69.08) 192.2,68.76 194.2,68.4 211.52,56.28 237.67,51.66 237.79,51.61 237.8,51.62 238.37,51.38 244.59,47.03 245.62,45.55 245.62,44.82 C59.1
PE_SLOT1_TX_C_DP<9>: length 121
  BOTTOM w0.135: U1.J2 133.69,77.96 133.69,76.52 134.06,76.15 134.06,75.67 135.24,74.49 142.61,74.49 142.78,74.65 156.84,74.65 158.5,74.36 160.73,72.79 191.11,67.44 v8(192.49,67.19) 194.29,66.88 211.21,55.03 236.36,50.59 238.33,49.21 238.37,48.95 238.19,48.69 238.28,48.18 238.7,47.88 239.21,47.97 239.4,48.23 239.66,48.28 240.98,47.35 241.41,46.74 241.63,45.5 241.63,44.82 C60.1
PE_SLOT1_TX_C_DP<10>: length 119
  BOTTOM w0.135: C61.1 237.67,44.82 237.67,45.58 237.56,46.21 232.15,50 210.68,53.78 193.89,65.53 160.08,71.5 157.7,73.16 156.07,73.45 v8(152.25,73.45) 143.28,73.45 142.22,72.39 134.27,72.39 133.5,73.15 133.5,74.83 132.09,76.24 132.09,77.96 U1.L2
PE_SLOT1_TX_C_DP<11>: length 116.8
  BOTTOM w0.135: C62.1 233.71,44.82 233.71,45.5 233.66,45.77 232.6,47.28 230.69,48.62 v8(220.58,50.4) 210.89,52.11 193.46,64.32 159.35,70.33 157.03,71.96 155.38,72.25 143.77,72.25 142.52,70.99 133.94,70.99 132.26,72.67 132.26,74.37 131.29,75.34 131.29,77.96 U1.M2
PE_SLOT1_TX_C_DP<12>: length 114.9
  BOTTOM w0.135: U1.P2 129.69,77.96 129.69,75.42 130.61,74.5 130.61,72.24 133.25,69.6 142.82,69.6 144.27,71.05 v8(152.3,71.05) 155.27,71.05 156.02,70.91 158.51,69.17 192.97,63.09 210.69,50.68 227.4,47.73 227.43,47.73 229.18,46.5 229.67,45.81 229.67,44.82 C63.1
PE_SLOT1_TX_C_DP<13>: length 112.5
  BOTTOM w0.135: C64.1 225.73,44.82 225.73,45.41 225.69,45.51 225.29,45.88 222.23,47.39 210.25,49.5 209.74,49.59 192.11,61.94 157.86,67.98 155.65,69.53 155.55,69.63 144.55,69.63 143.07,68.15 v8(138.76,68.15) 132.46,68.15 129.11,71.5 129.11,74.4 128.89,74.62 128.89,77.96 U1.R2
PE_SLOT1_TX_C_DP<14>: length 110.9
  BOTTOM w0.135: U1.U2 127.29,77.96 127.29,76.37 127.62,76.04 127.62,73.32 127.79,73.15 127.79,70.46 131.52,66.73 v8(139.75,66.73) 143.35,66.73 144.98,68.35 155.21,68.35 157.52,66.73 191.2,60.79 208.73,48.52 220.11,46.51 220.69,46.1 220.69,46.1 221.27,45.69 221.71,45.26 221.76,45.21 221.76,44.85 C65.1
PE_SLOT1_TX_C_DP<15>: length 110.8
  BOTTOM w0.135: C66.1 217.76,44.85 217.76,45.12 217.68,45.21 217.64,45.26 217.53,45.4 212.94,46.21 212.72,46.06 212.59,45.31 212.16,45.02 211.65,45.11 211.35,45.53 211.48,46.27 211.33,46.49 210.96,46.75 207.84,47.3 190.32,59.57 157.35,65.39 154.83,67.15 145.47,67.15 143.65,65.33 v8(136.58,65.33) 130.89,65.33 126.37,69.85 126.37,76.71 126.47,76.81 126.47,77.94 U1.V2
PE_SLOT1_TX_DN<0>: length 7.4
  BOTTOM w0.135: J1.B15 280.59,38.51 arc(280.65,38.55) 280.72,38.57 281.17,38.57 arc(281.76,38.81) 282,39.4 282,43.39 C31.2
PE_SLOT1_TX_DN<1>: length 7.5
  BOTTOM w0.135: J1.B20 275.25,39.33 arc(275.33,38.96) 275.01,38.74 274.58,38.74 arc(274.16,38.92) 273.98,39.34 273.98,40.41 274.16,40.59 274.16,41.03 273.98,41.21 273.98,41.65 274.16,41.82 274.16,42.26 273.98,42.44 273.98,43.34 C32.2
PE_SLOT1_TX_DN<2>: length 7.5
  BOTTOM w0.135: C33.2 269.98,43.34 269.98,42.44 270.16,42.26 270.16,41.82 269.98,41.65 269.98,41.21 270.16,41.03 270.16,40.59 269.98,40.41 269.98,39.34 arc(270.16,38.92) 270.58,38.74 271.01,38.74 arc(271.33,38.96) 271.25,39.33 J1.B24
PE_SLOT1_TX_DN<3>: length 7.5
  BOTTOM w0.135: C34.2 265.98,43.34 265.98,42.44 266.16,42.26 266.16,41.82 265.98,41.65 265.98,41.21 266.16,41.03 266.16,40.59 265.98,40.41 265.98,39.34 arc(266.16,38.92) 266.58,38.74 267.01,38.74 arc(267.33,38.96) 267.25,39.33 J1.B28
PE_SLOT1_TX_DN<4>: length 7.5
  BOTTOM w0.135: J1.B34 261.25,39.33 arc(261.33,38.96) 261.01,38.74 260.58,38.74 arc(260.16,38.92) 259.98,39.34 259.98,40.41 260.16,40.59 260.16,41.03 259.98,41.21 259.98,41.65 260.16,41.82 260.16,42.26 259.98,42.44 259.98,43.34 C67.2
PE_SLOT1_TX_DN<5>: length 7.5
  BOTTOM w0.135: C68.2 255.98,43.34 255.98,42.44 256.16,42.26 256.16,41.82 255.98,41.65 255.98,41.21 256.16,41.03 256.16,40.59 255.98,40.41 255.98,39.34 arc(256.16,38.92) 256.58,38.74 257.01,38.74 arc(257.33,38.96) 257.25,39.33 J1.B38
PE_SLOT1_TX_DN<6>: length 7.5
  BOTTOM w0.135: J1.B42 253.25,39.33 arc(253.33,38.96) 253.01,38.74 252.58,38.74 arc(252.16,38.92) 251.98,39.34 251.98,40.41 252.16,40.59 252.16,41.03 251.98,41.21 251.98,41.65 252.16,41.82 252.16,42.26 251.98,42.44 251.98,43.34 C69.2
PE_SLOT1_TX_DN<7>: length 7.5
  BOTTOM w0.135: C70.2 247.98,43.34 247.98,42.44 248.16,42.26 248.16,41.82 247.98,41.65 247.98,41.21 248.16,41.03 248.16,40.59 247.98,40.41 247.98,39.34 arc(248.16,38.92) 248.58,38.74 249.01,38.74 arc(249.33,38.96) 249.25,39.33 J1.B46
PE_SLOT1_TX_DN<8>: length 7.4
  BOTTOM w0.135: J1.B51 244.59,38.51 arc(244.65,38.55) 244.72,38.57 245.17,38.57 arc(245.76,38.81) 246,39.4 246,43.39 C71.2
PE_SLOT1_TX_DN<9>: length 7.4
  BOTTOM w0.135: C72.2 242,43.38 242,39.4 arc(241.76,38.81) 241.17,38.57 240.72,38.57 arc(240.65,38.55) 240.59,38.51 J1.B55
PE_SLOT1_TX_DN<10>: length 7.4
  BOTTOM w0.135: C73.2 238,43.34 238,39.4 arc(237.76,38.81) 237.17,38.57 236.72,38.57 arc(236.65,38.55) 236.59,38.51 J1.B59
PE_SLOT1_TX_DN<11>: length 7.4
  BOTTOM w0.135: J1.B63 232.59,38.51 arc(232.65,38.55) 232.72,38.57 233.17,38.57 arc(233.76,38.81) 234,39.4 234,43.3 C74.2
PE_SLOT1_TX_DN<12>: length 7.4
  BOTTOM w0.135: J1.B67 228.59,38.51 arc(228.65,38.55) 228.72,38.57 229.17,38.57 arc(229.76,38.81) 230,39.4 230,43.34 C75.2
PE_SLOT1_TX_DN<13>: length 7.4
  BOTTOM w0.135: C76.2 226,43.28 226,39.4 arc(225.76,38.81) 225.17,38.57 224.72,38.57 arc(224.65,38.55) 224.59,38.51 J1.B71
PE_SLOT1_TX_DN<14>: length 7.4
  BOTTOM w0.135: C77.2 222,43.28 222,39.4 arc(221.76,38.81) 221.17,38.57 220.72,38.57 arc(220.65,38.55) 220.59,38.51 J1.B75
PE_SLOT1_TX_DN<15>: length 7.4
  BOTTOM w0.135: J1.B79 216.59,38.51 arc(216.65,38.55) 216.72,38.57 217.17,38.57 arc(217.76,38.81) 218,39.4 218,43.28 C78.2
PE_SLOT1_TX_DP<0>: length 7.4
  BOTTOM w0.135: J1.B14 280.39,39.32 arc(280.34,39.03) 280.58,38.87 281.17,38.87 arc(281.54,39.03) 281.7,39.4 281.7,40.52 281.54,40.67 281.54,41.07 281.7,41.23 281.7,41.63 281.54,41.78 281.54,42.19 281.7,42.34 281.7,43.24 C27.2
PE_SLOT1_TX_DP<1>: length 7.5
  BOTTOM w0.135: J1.B19 275.83,37.76 arc(275.63,38.24) 275.15,38.44 274.58,38.44 arc(273.94,38.71) 273.68,39.34 273.68,43.29 C28.2
PE_SLOT1_TX_DP<2>: length 7.5
  BOTTOM w0.135: J1.B23 271.83,37.76 arc(271.63,38.24) 271.15,38.44 270.58,38.44 arc(269.94,38.71) 269.68,39.34 269.68,43.29 C29.2
PE_SLOT1_TX_DP<3>: length 7.5
  BOTTOM w0.135: J1.B27 267.83,37.76 arc(267.63,38.24) 267.15,38.44 266.58,38.44 arc(265.94,38.71) 265.68,39.34 265.68,43.29 C30.2
PE_SLOT1_TX_DP<4>: length 7.5
  BOTTOM w0.135: J1.B33 261.83,37.76 arc(261.63,38.24) 261.15,38.44 260.58,38.44 arc(259.94,38.71) 259.68,39.34 259.68,43.29 C55.2
PE_SLOT1_TX_DP<5>: length 7.5
  BOTTOM w0.135: C56.2 255.68,43.29 255.68,39.34 arc(255.94,38.71) 256.58,38.44 257.15,38.44 arc(257.63,38.24) 257.83,37.76 J1.B37
PE_SLOT1_TX_DP<6>: length 7.5
  BOTTOM w0.135: J1.B41 253.83,37.76 arc(253.63,38.24) 253.15,38.44 252.58,38.44 arc(251.94,38.71) 251.68,39.34 251.68,43.29 C57.2
PE_SLOT1_TX_DP<7>: length 7.5
  BOTTOM w0.135: C58.2 247.68,43.29 247.68,39.34 arc(247.94,38.71) 248.58,38.44 249.15,38.44 arc(249.63,38.24) 249.83,37.76 J1.B45
PE_SLOT1_TX_DP<8>: length 7.4
  BOTTOM w0.135: C59.2 245.7,43.24 245.7,42.34 245.54,42.19 245.54,41.78 245.7,41.63 245.7,41.23 245.54,41.07 245.54,40.67 245.7,40.52 245.7,39.4 arc(245.54,39.03) 245.17,38.87 244.58,38.87 arc(244.34,39.03) 244.39,39.32 J1.B50
PE_SLOT1_TX_DP<9>: length 7.4
  BOTTOM w0.135: C60.2 241.7,43.25 241.7,42.34 241.54,42.19 241.54,41.78 241.7,41.63 241.7,41.23 241.54,41.07 241.54,40.67 241.7,40.52 241.7,39.4 arc(241.54,39.03) 241.17,38.87 240.56,38.87 arc(240.33,39.03) 240.38,39.31 J1.B54
PE_SLOT1_TX_DP<10>: length 7.4
  BOTTOM w0.135: J1.B58 236.36,39.28 arc(236.31,39.02) 236.53,38.87 237.17,38.87 arc(237.54,39.03) 237.69,39.4 237.69,40.52 237.54,40.67 237.54,41.07 237.69,41.23 237.69,41.63 237.54,41.78 237.54,42.19 237.69,42.34 237.69,43.29 C61.2
PE_SLOT1_TX_DP<11>: length 7.4
  BOTTOM w0.135: C62.2 233.69,43.33 233.69,42.34 233.54,42.19 233.54,41.78 233.69,41.63 233.69,41.23 233.54,41.07 233.54,40.67 233.69,40.52 233.69,39.4 arc(233.54,39.03) 233.17,38.87 232.5,38.87 arc(232.29,39.01) 232.34,39.26 J1.B62
PE_SLOT1_TX_DP<12>: length 7.4
  BOTTOM w0.135: J1.B66 228.36,39.29 arc(228.31,39.02) 228.53,38.87 229.17,38.87 arc(229.54,39.03) 229.69,39.4 229.69,40.52 229.54,40.67 229.54,41.07 229.69,41.23 229.69,41.63 229.54,41.78 229.54,42.19 229.69,42.34 229.69,43.29 C63.2
PE_SLOT1_TX_DP<13>: length 7.4
  BOTTOM w0.135: C64.2 225.7,43.35 225.7,42.34 225.54,42.19 225.54,41.78 225.7,41.63 225.7,41.23 225.54,41.07 225.54,40.67 225.7,40.52 225.7,39.4 arc(225.54,39.03) 225.17,38.87 224.5,38.87 arc(224.29,39.01) 224.34,39.26 J1.B70
PE_SLOT1_TX_DP<14>: length 7.4
  BOTTOM w0.135: C65.2 221.7,43.35 221.7,42.34 221.54,42.19 221.54,41.78 221.7,41.63 221.7,41.23 221.54,41.07 221.54,40.67 221.7,40.52 221.7,39.4 arc(221.54,39.03) 221.17,38.87 220.5,38.87 arc(220.29,39.01) 220.34,39.26 J1.B74
PE_SLOT1_TX_DP<15>: length 7.4
  BOTTOM w0.135: J1.B78 216.34,39.26 arc(216.29,39.01) 216.5,38.87 217.17,38.87 arc(217.54,39.03) 217.7,39.4 217.7,40.52 217.54,40.67 217.54,41.07 217.7,41.23 217.7,41.63 217.54,41.78 217.54,42.19 217.7,42.34 217.7,43.35 C66.2
PE_SLOT2_PRES_N: length 107.3
  TOP w0.114: R45.2 127.84,110.36 130.1,112.62 153.4,112.62 156.67,109.35 160.06,109.35 191.93,77.47 208.66,77.47 210.36,79.17 212.68,79.17 213.45,78.39 J2.B81
PE_SLOT2_RX_DN<0>: length 181
  IN2 w0.089: 126.37,95.98 126.36,95.96 126.32,95.92 126.3,95.79 126.3,93.34 v5(126.49,93.16)
  IN2 w0.145: J2.A17 278.2,75.15 278.39,75.08 278.54,75.16 278.66,75.28 278.66,78.86 277.67,79.84 277.67,80.85 278.07,83.07 277.72,85.03 277.49,85.37 277.34,85.39 276.96,85.94 276.98,86.08 276.65,86.56 276.53,86.58 276.13,87.15 276.15,87.27 275.82,87.75 275,88.27 274.89,88.25 274.39,88.57 274.37,88.67 273.67,89.12 272.89,89.25 272.89,89.25 212.11,99.97 206.66,99.01 194.05,101.23 190.58,100.62 173.35,103.66 167.71,107.61 167.54,107.58 167,107.96 166.97,108.13 166.5,108.46 166.32,108.43 165.8,108.8 165.76,108.97 165.24,109.34 163.35,109.67 163.24,109.59 162.51,109.72 162.44,109.83 161.87,109.93 161.77,109.86 161.03,109.99 160.96,110.09 160.39,110.19 160.27,110.11 159.56,110.23 159.48,110.35 158.91,110.45 158.8,110.38 158.07,110.51 158,110.61 157.43,110.72 157.28,110.61 156.63,110.72 156.52,110.88 155.95,110.98 155.81,110.88 155.14,111 155.04,111.14 153.71,111.37 152.07,111.37 152.06,111.37 151.92,111.37 144.78,110.11 144.7,109.99 144.01,109.87 143.89,109.95 143.32,109.85 143.22,109.71 142.57,109.59 142.43,109.69 141.85,109.59 140.11,108.38 140.09,108.24 139.51,107.84 139.37,107.86 137.58,106.61 135.65,106.27 135.55,106.12 134.91,106.01 134.76,106.11 134.19,106.01 134.09,105.87 133.45,105.75 133.31,105.85 132.7,105.75 129.34,103.39 129.12,103.07 129.15,102.87 128.82,102.4 128.62,102.36 128.29,101.89 128.32,101.69 127.99,101.21 127.79,101.18 127.46,100.7 127.49,100.5 127.16,100.03 126.96,99.99 126.69,99.61 126.62,98.85 126.73,98.72 126.67,98.06 126.54,97.96 126.49,97.38 126.62,97.23 126.56,96.62 126.41,96.49 126.37,95.98
  BOTTOM w0.135: U1.V20 v5(126.49,93.16)
PE_SLOT2_RX_DN<1>: length 180.3
  IN2 w0.089: 127.51,95.11 127.5,95.09 127.45,95.07 127.4,94.94 126.86,94.18 126.86,93.79 127.1,93.55 127.1,93.34 v5(127.29,93.16)
  IN2 w0.145: J2.A22 273.2,74.64 273.14,74.83 272.95,74.93 272.69,75.19 272.69,78.89 273.66,79.87 273.66,81.32 273.53,81.45 273.53,82.12 273.66,82.25 273.66,82.83 273.53,82.96 273.53,83.62 273.66,83.75 273.66,84.33 273.55,84.45 273.55,85.15 273.66,85.26 273.66,85.57 273.54,86.31 273.05,87 272.1,87.66 272,87.65 271.37,88.09 271.35,88.19 270.36,88.88 267.55,89.38 212.25,99.13 206.77,98.16 194.35,100.35 190.63,99.69 172.9,102.82 168.28,106.05 164.52,106.72 164.39,106.62 163.7,106.74 163.6,106.88 162.9,107 152.28,105.13 148.85,105.74 148.56,106.15 148.82,107.63 148.7,107.8 148.34,107.86 148.18,107.75 147.91,106.26 147.5,105.97 147.01,106.06 146.72,106.47 146.98,107.95 146.86,108.12 146.51,108.19 146.34,108.07 146.08,106.58 145.62,106.26 144.49,106.46 141.12,105.87 141.02,105.73 140.38,105.62 140.24,105.71 139.67,105.61 139.6,105.51 138.9,105.38 138.79,105.46 138.22,105.36 138.14,105.23 137.47,105.12 137.34,105.2 136.77,105.1 136.68,104.97 136.03,104.85 135.89,104.95 135.32,104.85 135.22,104.7 134.59,104.59 134.44,104.69 133.05,104.44 131.92,103.66 131.9,103.52 131.32,103.12 131.19,103.14 129.85,102.21 129.06,101.08 129.09,100.94 128.69,100.37 128.55,100.35 128.22,99.87 128.12,99.32 128.22,99.17 128.11,98.52 127.96,98.42 127.86,97.85 127.95,97.72 127.83,97.04 127.7,96.95 127.6,96.39 127.69,95.91 127.57,95.25 127.51,95.11
  BOTTOM w0.135: U1.U20 v5(127.29,93.16)
PE_SLOT2_RX_DN<2>: length 166.9
  IN2 w0.089: 128.75,96.34 128.75,96.32 128.7,96.28 128.7,93.34 v5(128.89,93.16)
  IN2 w0.145: J2.A26 269.21,74.66 269.15,74.82 269.14,74.84 268.95,74.93 268.72,75.16 268.72,78.93 269.66,79.87 269.66,80.8 269.85,81.85 270.03,82.89 269.62,85.23 268.54,86.77 265.47,88.92 212.46,98.26 206.59,97.23 194.23,99.41 189.99,98.66 172.03,101.83 167.77,104.81 162.14,105.8 160.93,105.59 160.93,105.59 160.36,105.49 160.27,105.36 159.61,105.25 159.49,105.33 158.92,105.23 158.83,105.11 158.17,104.99 158.05,105.08 157.48,104.98 157.39,104.85 156.73,104.74 156.61,104.83 156.04,104.72 155.95,104.6 155.3,104.48 155.17,104.57 154.6,104.47 154.51,104.35 153.86,104.23 153.73,104.32 152.04,104.02 144.39,105.37 142.71,105.07 142.63,104.97 141.92,104.84 141.82,104.91 141.25,104.81 141.17,104.71 140.46,104.58 140.36,104.66 139.79,104.56 139.71,104.44 139.01,104.32 138.9,104.4 138.33,104.3 138.25,104.19 137.55,104.06 137.44,104.14 136.87,104.04 136.79,103.93 136.09,103.8 135.98,103.88 135.41,103.78 135.31,103.65 134.65,103.53 134.52,103.63 133.51,103.45 133.01,103.1 132.98,102.92 132.42,102.53 132.24,102.56 131.76,102.23 131.73,102.05 131.16,101.66 130.99,101.69 130.58,101.4 130.19,100.84 130.22,100.69 129.83,100.13 129.67,100.1 129.29,99.55 129.18,98.93 129.29,98.78 129.18,98.17 129.17,98.15 129.02,98.04 128.75,96.49 128.75,96.34
  BOTTOM w0.135: U1.R20 v5(128.89,93.16)
PE_SLOT2_RX_DN<3>: length 164.6
  IN2 w0.089: 129.82,95.85 129.81,95.82 129.76,95.79 129.67,95.28 129.29,94.74 129.26,94.56 129.26,93.59 v5(129.69,93.16)
  IN2 w0.145: 129.82,95.85 129.9,96.32 130.02,96.4 130.14,97.06 130.05,97.18 130.15,97.75 130.29,97.85 130.4,98.48 130.3,98.61 130.42,99.29 131.49,100.8 131.81,101.03 132,100.99 132.5,101.34 132.53,101.54 133.7,102.35 134.66,102.52 134.79,102.43 135.44,102.55 135.53,102.68 136.11,102.78 136.23,102.69 136.89,102.8 136.98,102.93 137.55,103.03 137.68,102.94 138.33,103.06 138.42,103.19 138.99,103.29 139.12,103.2 139.77,103.31 139.86,103.44 144.47,104.25 152.52,102.83 153.83,103.06 153.97,102.97 154.61,103.08 154.7,103.22 155.27,103.32 155.37,103.25 156.07,103.37 156.13,103.47 156.7,103.57 156.83,103.48 157.48,103.6 157.57,103.72 158.14,103.82 158.23,103.76 158.94,103.88 159,103.98 161.82,104.47 162.1,104.47 167.19,103.57 171.17,100.79 175.09,100.1 175.24,99.88 175.2,99.63 175.49,99.22 175.98,99.14 176.39,99.42 176.43,99.67 176.65,99.82 176.92,99.77 177.08,99.55 177.03,99.31 177.32,98.9 177.82,98.81 178.23,99.1 178.27,99.34 178.49,99.5 178.76,99.45 178.91,99.23 178.87,98.99 179.16,98.57 179.65,98.49 180.06,98.78 180.11,99.02 180.33,99.17 180.6,99.13 180.75,98.9 180.71,98.66 181,98.25 181.49,98.16 181.9,98.45 181.94,98.69 182.17,98.85 189.82,97.5 194.57,98.34 206.46,96.24 212.87,97.37 260.84,88.91 261.44,88.49 261.46,88.36 262.04,87.96 262.17,87.98 262.65,87.65 262.66,87.6 263.33,87.12 263.38,87.13 264.41,86.41 265.66,84.62 265.66,83.82 265.57,83.72 265.57,82.97 265.66,82.88 265.66,82.3 265.56,82.19 265.56,81.46 265.66,81.35 265.66,79.87 264.69,78.89 264.69,75.19 264.95,74.93 265.14,74.83 265.14,74.83 265.2,74.63 J2.A30
  BOTTOM w0.135: U1.P20 v5(129.69,93.16)
PE_SLOT2_RX_DN<4>: length 154.1
  IN2 w0.145: v5(132.09,93.16) 131.83,92.9 131.62,92.9 131.4,93.12 131.4,93.62 131.47,93.68 131.47,94.48 131.4,94.55 131.4,95.12 131.5,95.22 131.5,95.96 131.4,96.05 131.4,96.63 131.5,96.73 131.5,97.46 131.4,97.56 131.4,98.08 131.43,98.25 132.36,99.58 132.72,99.83 133.84,100.03 134.72,99.87 135.45,99.98 136.92,101.01 137.04,101.06 140.66,101.7 140.8,101.6 141.49,101.73 141.58,101.86 142.15,101.96 142.28,101.87 142.98,101.99 143.07,102.12 143.64,102.22 143.76,102.14 144.48,102.27 144.56,102.38 145.13,102.49 145.24,102.4 145.97,102.53 146.05,102.65 146.79,102.78 152.56,101.76 160.17,103.1 160.32,103.1 160.32,103.1 162.82,103.1 166.63,102.43 171.53,99 179.03,97.67 179.04,97.67 179.61,97.57 179.7,97.43 180.38,97.31 180.52,97.41 181.09,97.31 181.18,97.18 181.87,97.06 182,97.15 182.57,97.05 182.68,96.9 183.34,96.78 183.49,96.89 184.97,96.62 184.97,96.63 187.59,96.17 194.57,97.4 206.24,95.34 213,96.53 256.48,88.86 256.53,88.8 257.32,88.66 257.39,88.7 258.16,88.57 258.83,88.1 259.34,87.37 259.5,86.45 259.66,85.52 259.66,79.87 258.71,78.92 258.71,75.17 258.95,74.93 259.14,74.84 259.15,74.82 259.21,74.66 J2.A36
  BOTTOM w0.124: U1.M20 v5(132.09,93.16)
PE_SLOT2_RX_DN<5>: length 153.8
  IN2 w0.089: v5(132.89,93.16) 132.62,93.43 132.62,93.54 132.45,93.71 132.34,93.71 132.17,93.88 132.17,94.07 132.25,94.15 132.25,94.44 132.17,94.53 132.17,94.8 132.26,94.89 132.26,95.25 132.17,95.34 132.17,95.51 132.58,96.51 132.64,96.54 132.66,96.56
  IN2 w0.145: J2.A40 255.21,74.66 255.15,74.82 255.14,74.84 254.95,74.93 254.7,75.18 254.7,78.9 255.66,79.87 255.66,86.11 255.47,87.23 255.03,87.86 254.4,88.3 212.78,95.64 206.16,94.47 194.55,96.52 187.09,95.2 177.78,96.84 177.69,96.78 176.97,96.91 176.91,96.99 176.34,97.1 176.23,97.02 175.55,97.14 175.47,97.25 174.9,97.35 174.81,97.29 174.1,97.41 174.03,97.5 173.46,97.6 173.39,97.55 172.65,97.68 172.59,97.76 171.38,97.97 166.25,101.56 162.42,102.24 158.43,101.53 158.36,101.43 157.58,101.29 157.48,101.36 156.91,101.26 156.83,101.15 156.06,101.02 155.95,101.1 155.38,100.99 155.3,100.89 154.53,100.75 154.43,100.83 153.85,100.73 153.78,100.62 153,100.48 152.9,100.56 152.33,100.46 152.26,100.36 151.47,100.22 151.37,100.29 149.55,99.97 149.14,100.25 148.92,101.47 148.75,101.59 148.4,101.52 148.28,101.36 148.49,100.14 148.2,99.73 147.71,99.64 147.3,99.93 147,101.64 146.78,101.8 146.51,101.75 146.35,101.53 146.66,99.82 146.37,99.4 145.47,99.25 143.61,99.58 143.48,99.48 142.79,99.61 142.7,99.74 142.13,99.84 142.02,99.75 141.3,99.88 141.22,100 140.49,100.13 140.06,100.05 140.01,99.97 139.34,99.85 139.26,99.91 138.71,99.81 138.38,99.58 138.34,99.39 137.87,99.06 137.69,99.1 136.37,98.17 135.36,97.99 135.31,97.91 134.57,97.78 134.48,97.84 134.03,97.76 133.84,97.62 133.81,97.49 133.43,97.22 133.29,97.24 132.99,97.03 132.66,96.56
  BOTTOM w0.135: U1.L20 v5(132.89,93.16)
PE_SLOT2_RX_DN<6>: length 140.3
  IN2 w0.089: 133.69,95.6 133.69,95.58 133.65,95.53 133.65,95.23 133.72,95.16 133.72,94.66 133.65,94.58 133.65,94.07 133.8,93.92 133.9,93.92 134.18,93.64 134.18,93.54 134.32,93.4 134.32,93.33 v5(134.49,93.16)
  IN2 w0.145: 133.69,95.6 133.69,95.8 133.76,96.17 134.13,96.71 134.67,97.08 136.54,97.41 136.65,97.34 137.32,97.46 137.4,97.57 137.97,97.67 138.08,97.59 138.75,97.71 138.82,97.82 140.35,98.08 142.29,97.74 142.96,97.86 143.08,97.78 143.77,97.9 143.88,98.05 144.39,98.14 144.56,98.02 145.23,98.14 145.35,98.31 145.86,98.4 146.05,98.26 146.68,98.37 146.81,98.57 147.33,98.66 147.5,98.54 148.16,98.65 148.28,98.83 159.02,100.72 159.15,100.63 159.82,100.75 159.91,100.88 160.68,101.01 160.82,101.01 160.82,101.01 161.43,101.01 161.53,100.91 162.21,100.91 162.31,101.01 163.37,101.01 164.1,100.88 164.18,100.77 164.88,100.65 164.99,100.73 165.91,100.56 170.98,97.02 172,96.84 172.11,96.68 172.78,96.56 172.94,96.67 186.58,94.27 194.3,95.63 206.43,93.53 213.26,94.74 246.32,88.91 246.41,88.78 247.13,88.65 247.26,88.74 247.83,88.64 247.92,88.51 248.64,88.38 248.77,88.47 249.67,88.32 250.93,87.44 251.42,86.73 251.54,86.04 251.66,85.34 251.66,79.87 250.72,78.93 250.72,75.16 250.95,74.93 251.14,74.84 251.15,74.82 251.21,74.66 J2.A44
  BOTTOM w0.135: U1.J20 v5(134.49,93.16)
PE_SLOT2_RX_DN<7>: length 140.2
  IN2 w0.089: 135.17,94.94 135.16,94.92 135.12,94.88 135.1,94.74 135.1,94.43 135.17,94.36 135.17,93.83 135.1,93.76 135.1,93.34 v5(135.29,93.16)
  IN2 w0.145: 135.17,94.94 135.22,95.51 135.58,96.03 136.26,96.51 136.7,96.58 136.87,96.46 137.37,96.55 137.49,96.72 137.99,96.81 138.16,96.69 138.66,96.78 138.78,96.95 139.74,97.12 140.59,96.97 140.69,96.82 141.29,96.72 141.43,96.82 142.33,96.66 143.1,96.8 143.22,96.72 143.28,96.73 144.17,96.88 144.25,97 144.89,97.11 144.98,97.05 145.74,97.18 145.81,97.27 146.4,97.38 146.49,97.32 147.25,97.45 147.31,97.54 147.91,97.64 148.03,97.56 148.62,97.66 148.7,97.79 149.19,97.87 149.32,97.79 149.9,97.89 149.99,98.01 150.48,98.1 150.6,98.01 151.19,98.12 151.28,98.24 151.76,98.33 151.89,98.24 152.48,98.34 152.56,98.47 153.05,98.55 153.17,98.47 153.76,98.57 153.85,98.69 154.34,98.78 154.46,98.69 155.05,98.8 155.13,98.92 155.66,99.01 155.76,98.94 156.29,99.03 156.36,99.14 156.76,99.21 156.97,99.06 157.05,98.58 156.97,98.46 157.05,98.05 157.16,97.97 157.25,97.46 157.61,97.21 158.19,97.32 158.44,97.67 158.16,99.27 158.32,99.49 158.58,99.54 158.81,99.38 159.09,97.76 159.45,97.51 160.03,97.61 160.28,97.97 160,99.59 160.15,99.81 160.83,99.93 166.54,98.93 170.77,95.96 186.17,93.25 194.57,94.73 206.22,92.68 213.26,93.92 244.44,88.42 245.48,87.69 246.78,85.84 247.68,80.75 247.68,79.95 246.69,78.96 246.69,75.19 246.95,74.93 247.14,74.84 247.15,74.82 247.21,74.66 J2.A48
  BOTTOM w0.135: U1.H20 v5(135.29,93.16)
PE_SLOT2_RX_DN<8>: length 121.1
  IN2 w0.145: J2.A53 242.2,75.15 242.4,75.08 242.54,75.16 242.67,75.29 242.67,78.9 241.69,79.88 241.69,85.64 240.17,87.82 236.46,88.47 236.04,89.08 234.59,89.34 234.4,89.2 233.95,89.28 233.81,89.47 233.37,89.55 233.18,89.42 232.73,89.49 232.6,89.69 213.26,93.1 206.22,91.86 194.68,93.89 186.17,92.39 181.15,93.28 181.03,93.19 180.34,93.32 180.26,93.43 179.69,93.53 179.56,93.44 178.9,93.56 178.8,93.69 178.23,93.79 178.11,93.7 177.43,93.82 177.35,93.95 176.78,94.05 176.64,93.95 175.98,94.07 175.89,94.2 175.32,94.3 175.21,94.22 174.51,94.35 174.43,94.46 173.86,94.56 173.77,94.5 173.04,94.62 172.98,94.72 172.41,94.82 172.4,94.82 170.17,95.21 168.03,96.71 164.24,97.38 157.59,96.21 151.5,97.28 150.77,97.16 150.67,97.01 150.2,96.93 150.05,97.03 149.63,96.95 149.54,96.82 149.04,96.73 148.91,96.83 148.49,96.75 148.4,96.62 147.9,96.53 147.77,96.63 147.35,96.55 147.26,96.42 146.76,96.33 146.63,96.43 146.21,96.35 146.12,96.22 145.62,96.13 145.49,96.22 145.07,96.15 144.98,96.02 144.48,95.93 144.34,96.02 143.93,95.95 143.83,95.82 143.34,95.73 143.28,95.76 143.2,95.82 142.55,95.71 141.33,95.92 138.63,95.92 138.49,95.78 v5(138.49,95.56)
  BOTTOM w0.135: U1.D23 v5(138.49,95.56)
PE_SLOT2_RX_DN<9>: length 119.7
  IN2 w0.089: v5(138.49,94.76) 138.88,95.15 139.7,95.15 139.79,95.06 140.14,95.06 140.23,95.15 140.59,95.15 140.68,95.06 141.03,95.06 141.12,95.15 141.66,95.15 141.7,95.1 141.72,95.1
  IN2 w0.145: 141.72,95.1 141.87,95.1 143.28,94.85 143.29,94.85 143.43,94.85 143.43,94.86 143.46,94.86 144.31,95.01 144.47,94.89 145.14,95.01 145.25,95.17 145.76,95.26 145.88,95.18 146.62,95.31 146.71,95.43 147.22,95.52 147.31,95.45 148.09,95.59 148.16,95.68 148.67,95.77 148.77,95.7 149.53,95.83 149.61,95.94 150.12,96.03 150.22,95.96 150.99,96.1 151.06,96.2 151.93,96.35 157.68,95.34 163.83,96.42 164.49,96.42 167.71,95.85 169.98,94.27 170.85,94.11 170.93,94 171.62,93.87 171.74,93.96 172.31,93.85 172.4,93.72 173.06,93.61 173.19,93.7 173.76,93.6 173.86,93.47 174.52,93.35 174.65,93.44 175.22,93.34 175.29,93.24 176,93.11 176.11,93.18 176.68,93.08 176.76,92.96 177.44,92.84 177.56,92.93 178.13,92.83 178.22,92.71 178.9,92.59 179.02,92.67 179.59,92.57 179.66,92.46 180.37,92.34 180.47,92.41 181.04,92.31 181.12,92.2 181.82,92.08 181.93,92.16 185.82,91.47 194.79,93.05 194.87,93.04 206.22,91.04 212.7,92.18 227.71,89.53 227.84,89.34 228.29,89.26 228.48,89.4 228.93,89.32 229.06,89.13 229.5,89.05 229.7,89.18 230.26,89.08 231.32,88.34 232.04,87.84 235.93,87.16 236.69,86.63 237.45,85.53 237.67,84.31 237.67,83.09 238.02,82.73 239.48,82.73 239.68,82.54 239.68,82.27 239.48,82.08 238.02,82.08 237.67,81.72 237.67,79.92 238.69,78.9 238.69,75.31 238.54,75.16 238.4,75.08 238.2,75.15 J2.A57
  BOTTOM w0.135: U1.D22 v5(138.49,94.76)
PE_SLOT2_RX_DN<10>: length 112
  IN2 w0.089: v5(138.49,93.16) 138.88,93.55 139.18,93.55 139.82,93.66 140.4,94.07 140.88,94.15 141.01,94.18 141.07,94.14 141.09,94.14
  IN2 w0.145: J2.A61 234.2,75.15 234.4,75.08 234.54,75.16 234.66,75.28 234.66,78.9 233.73,79.84 233.73,81.92 233.37,83.98 233.44,84.41 233.17,85.94 232.97,86.23 232.12,86.82 228.84,87.4 227.02,88.67 225.88,88.87 225.77,88.8 225.1,88.92 225.02,89.03 224.45,89.13 224.35,89.06 223.66,89.18 223.59,89.28 223.02,89.38 222.9,89.29 222.24,89.41 222.16,89.53 217.29,90.39 217.29,90.39 212.42,91.25 206.13,90.14 194.63,92.17 185.44,90.55 180.27,91.45 180.16,91.37 179.49,91.49 179.41,91.61 178.84,91.71 178.74,91.64 178.04,91.76 177.97,91.86 177.4,91.96 177.29,91.88 176.61,92 176.53,92.12 175.96,92.22 175.83,92.13 175.18,92.24 175.09,92.37 174.52,92.47 174.39,92.38 173.75,92.49 173.65,92.62 173.08,92.72 173,92.67 172.27,92.8 172.22,92.88 171.65,92.98 171.54,92.9 170.85,93.03 170.78,93.13 169.18,93.41 167.6,94.52 164.41,95.08 164.3,95 163.51,95.13 163.43,95.25 162.72,95.38 160.45,94.98 160.37,94.86 159.71,94.74 159.59,94.83 159.02,94.72 158.95,94.62 158.26,94.5 158.16,94.57 157.55,94.46 152.58,95.34 152.12,95.26 152.12,95.26 151.65,95.18 151.57,95.05 150.87,94.93 150.75,95.02 150.17,94.92 150.09,94.79 149.39,94.67 149.27,94.76 148.7,94.65 148.6,94.52 147.92,94.4 147.79,94.49 147.22,94.39 147.13,94.27 146.43,94.15 146.31,94.23 145.74,94.13 145.64,94 144.96,93.88 144.83,93.97 144.25,93.87 143.28,94.04 141.89,94.28 141.09,94.14
  BOTTOM w0.135: U1.D20 v5(138.49,93.16)
